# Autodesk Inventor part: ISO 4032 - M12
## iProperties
Created: 2001-12
Part Number: ISO 4032 - M12
Catalog Web Link: file:///F:/Cad/Autodesk/Inventor 5/Content/Iso/index.htm?doNavigateId=81B6DECA-D49F-45EF-94B6-61B88B49772D|F0100A5F59104064B8BFC37D67EBD9B|true
Description: Hex Nut
Document SubType Name: Standard Catalog Part
Standard: ISO 4032 - M12
Designer: Tobben
Density: 1 g/cm^3
Control State: 0
Master: False
Checked Out: False
Shininess: 64.0
Angle Display Precision: 2
Document Length Units: 11269
Document Angle Units: 11279
Document Time Units: 11290
Document Mass Units: 11283
Document Length Units Precision: 3
Document Angle Units Precision: 2
Compacted: True
CLASSIFICATION: 31161727 un/spsc
MANUFACTURER: ISO Standard System
Density: 0.0
Volumn: 0.0
Area: 0.0
PropertySet Name: Model Information
Author: Tobben
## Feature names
1. Base1
